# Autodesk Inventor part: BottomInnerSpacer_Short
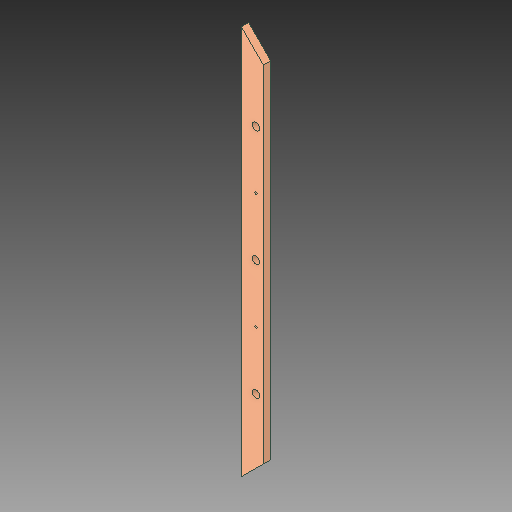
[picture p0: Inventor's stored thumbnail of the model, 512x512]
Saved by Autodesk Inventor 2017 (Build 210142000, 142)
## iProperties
Created: 2017-05
Part Number: BottomInnerSpacer_Short
Material: Generic
Document SubType Name: Modeling
Designer: Savy
Density: 1 g/cm^3
Appearance: Default
Mass: 302.112 g
Surface Area: 669.136 cm^2
Volume: 302.112 cm^3
Author: Savy
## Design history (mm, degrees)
feature "SOLID1"
body "Solid1"
